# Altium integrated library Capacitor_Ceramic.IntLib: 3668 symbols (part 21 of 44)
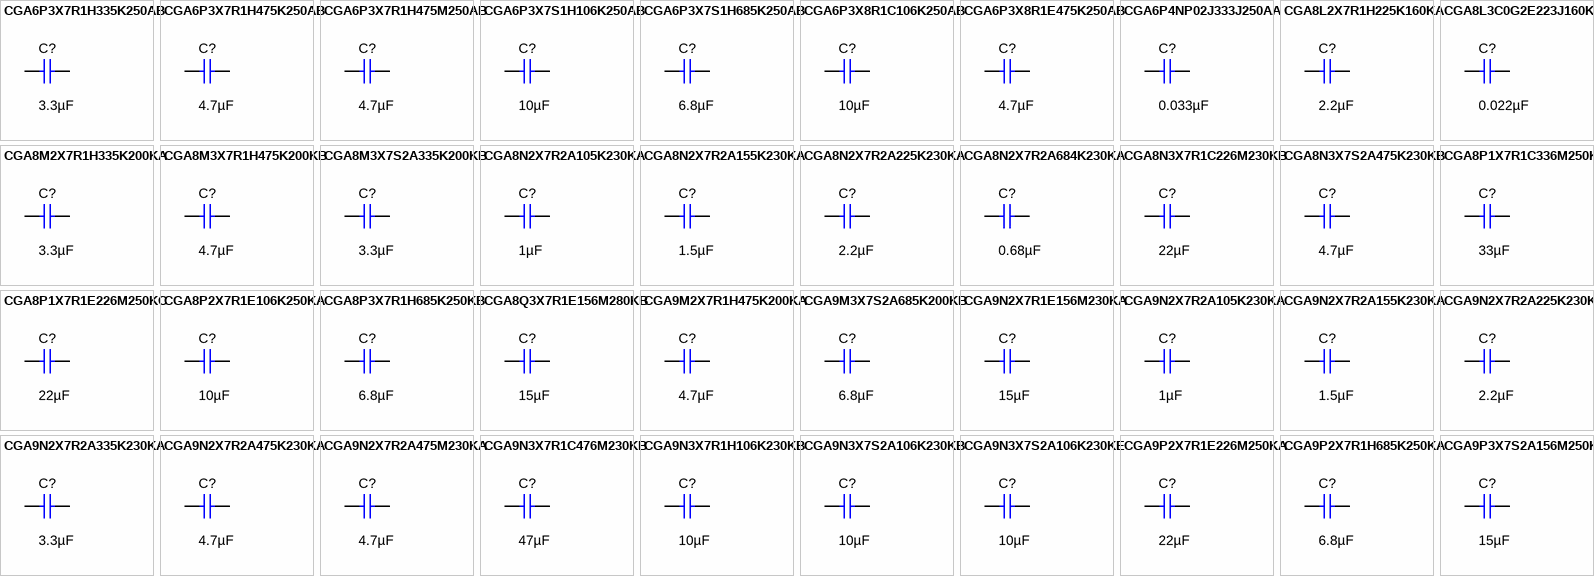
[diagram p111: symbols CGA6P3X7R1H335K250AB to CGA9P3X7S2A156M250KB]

## CGA8L3C0G2E223J160KA
designator C?  ValueDisplayed: 0.022µF  (hidden comment: CGA8L3C0G2E223J160KA)
CAP, CERM, 0.022 µF, 250 V,+/- 5%, C0G/NP0, AEC-Q200 Grade 1, 1812; Manufacturer: TDK; Polarized: N; CompType: Capacitor; Value: 0.022uF; U/M: EA; Cap_F: 0.000000022; Tolerance_%: 5; VDC_V: 250; Value2: 250V; TaMin_C: -55; TaMax_C: 125; Cap_Case: 1812; SizeArea_mm2: 14.4; SizeAreaWB_mm2: 23.1; SizeX_mm: 4.5; SizeY_mm: 3.2; SizeZ_mm: 2.54; AEC Category: Q200; AEC Qualified: Y; AEC Grade: 1
signal-integrity model Cap
simulation model Cap
footprint 1812_254
pins: 1, 2

## CGA8M2X7R1H335K200KA
designator C?  ValueDisplayed: 3.3µF  (hidden comment: CGA8M2X7R1H335K200KA)
CAP, CERM, 3.3 µF, 50 V,+/- 10%, X7R, AEC-Q200 Grade 1, 1812; Manufacturer: TDK; Polarized: N; CompType: Capacitor; Value: 3.3uF; U/M: EA; Cap_F: 0.0000033; Tolerance_%: 10; ESR_ohm: 0.004024; Value1: 0.004024 ohm; VDC_V: 50; Value2: 50V; IRMS_A: 3.82481; TaMin_C: -55; TaMax_C: 125; Cap_Case: 1812; SizeArea_mm2: 14.4; SizeAreaWB_mm2: 23.1; SizeX_mm: 4.5; SizeY_mm: 3.2; SizeZ_mm: 2.2; AEC Category: Q200; AEC Qualified: Y; AEC Grade: 1
signal-integrity model Cap
simulation model Cap
footprint 1812_220
footprint 1812_220M
footprint 1812_220L
pins: 1, 2

## CGA8M3X7R1H475K200KB
designator C?  ValueDisplayed: 4.7µF  (hidden comment: CGA8M3X7R1H475K200KB)
CAP, CERM, 4.7 µF, 50 V,+/- 10%, X7R, AEC-Q200 Grade 1, 1812; Manufacturer: TDK; Polarized: N; CompType: Capacitor; Value: 4.7uF; U/M: EA; Cap_F: 0.0000047; Tolerance_%: 10; ESR_ohm: 0.005172; Value1: 0.005172 ohm; VDC_V: 50; Value2: 50V; IRMS_A: 3.37342; TaMin_C: -55; TaMax_C: 125; Cap_Case: 1812; SizeArea_mm2: 14.4; SizeAreaWB_mm2: 23.1; SizeX_mm: 4.5; SizeY_mm: 3.2; SizeZ_mm: 2.2; AEC Category: Q200; AEC Qualified: Y; AEC Grade: 1
signal-integrity model Cap
simulation model Cap
footprint 1812_220
footprint 1812_220M
footprint 1812_220L
pins: 1, 2

## CGA8M3X7S2A335K200KB
designator C?  ValueDisplayed: 3.3µF  (hidden comment: CGA8M3X7S2A335K200KB)
CAP, CERM, 3.3 µF, 100 V,+/- 10%, X7S, AEC-Q200 Grade 1, 1812; Manufacturer: TDK; Polarized: N; CompType: Capacitor; Value: 3.3uF; U/M: EA; Cap_F: 0.0000033; Tolerance_%: 10; ESR_ohm: 0.004622; Value1: 0.004622 ohm; VDC_V: 100; Value2: 100V; IRMS_A: 3.5689; TaMin_C: -55; TaMax_C: 125; Cap_Case: 1812; SizeArea_mm2: 14.4; SizeAreaWB_mm2: 23.1; SizeX_mm: 4.5; SizeY_mm: 3.2; SizeZ_mm: 2.2; AEC Category: Q200; AEC Qualified: Y; AEC Grade: 1
signal-integrity model Cap
simulation model Cap
footprint 1812_220
footprint 1812_220M
footprint 1812_220L
pins: 1, 2

## CGA8N2X7R2A105K230KA
designator C?  ValueDisplayed: 1µF  (hidden comment: CGA8N2X7R2A105K230KA)
CAP, CERM, 1 µF, 100 V,+/- 10%, X7R, AEC-Q200 Grade 1, 1812; Manufacturer: TDK; Polarized: N; CompType: Capacitor; Value: 1uF; U/M: EA; Cap_F: 0.000001; Tolerance_%: 10; ESR_ohm: 0.005865; Value1: 0.005865 ohm; VDC_V: 100; Value2: 100V; IRMS_A: 3.17165; TaMin_C: -55; TaMax_C: 125; Cap_Case: 1812; SizeArea_mm2: 14.4; SizeAreaWB_mm2: 23.1; SizeX_mm: 4.5; SizeY_mm: 3.2; SizeZ_mm: 2.54; AEC Category: Q200; AEC Qualified: Y; AEC Grade: 1
signal-integrity model Cap
simulation model Cap
footprint 1812_254
pins: 1, 2

## CGA8N2X7R2A155K230KA
designator C?  ValueDisplayed: 1.5µF  (hidden comment: CGA8N2X7R2A155K230KA)
CAP, CERM, 1.5 µF, 100 V,+/- 10%, X7R, AEC-Q200 Grade 1, 1812; Manufacturer: TDK; Polarized: N; CompType: Capacitor; Value: 1.5uF; U/M: EA; Cap_F: 0.0000015; Tolerance_%: 10; ESR_ohm: 0.00449; Value1: 0.00449 ohm; VDC_V: 100; Value2: 100V; IRMS_A: 3.62321; TaMin_C: -55; TaMax_C: 125; Cap_Case: 1812; SizeArea_mm2: 14.4; SizeAreaWB_mm2: 23.1; SizeX_mm: 4.5; SizeY_mm: 3.2; SizeZ_mm: 2.54; AEC Category: Q200; AEC Qualified: Y; AEC Grade: 1
signal-integrity model Cap
simulation model Cap
footprint 1812_254
pins: 1, 2

## CGA8N2X7R2A225K230KA
designator C?  ValueDisplayed: 2.2µF  (hidden comment: CGA8N2X7R2A225K230KA)
CAP, CERM, 2.2 µF, 100 V,+/- 10%, X7R, AEC-Q200 Grade 1, 1812; Manufacturer: TDK; Polarized: N; CompType: Capacitor; Value: 2.2uF; U/M: EA; Cap_F: 0.0000022; Tolerance_%: 10; ESR_ohm: 0.002981; Value1: 0.002981 ohm; VDC_V: 100; Value2: 100V; IRMS_A: 4.44466; TaMin_C: -55; TaMax_C: 125; Cap_Case: 1812; SizeArea_mm2: 14.4; SizeAreaWB_mm2: 23.1; SizeX_mm: 4.5; SizeY_mm: 3.2; SizeZ_mm: 2.54; AEC Category: Q200; AEC Qualified: Y; AEC Grade: 1
signal-integrity model Cap
simulation model Cap
footprint 1812_254
pins: 1, 2

## CGA8N2X7R2A684K230KA
designator C?  ValueDisplayed: 0.68µF  (hidden comment: CGA8N2X7R2A684K230KA)
CAP, CERM, 0.68 µF, 100 V,+/- 10%, X7R, AEC-Q200 Grade 1, 1812; Manufacturer: TDK; Polarized: N; CompType: Capacitor; Value: 0.68uF; U/M: EA; Cap_F: 0.00000068; Tolerance_%: 10; ESR_ohm: 0.007113; Value1: 0.007113 ohm; VDC_V: 100; Value2: 100V; IRMS_A: 2.8819; TaMin_C: -55; TaMax_C: 125; Cap_Case: 1812; SizeArea_mm2: 14.4; SizeAreaWB_mm2: 23.1; SizeX_mm: 4.5; SizeY_mm: 3.2; SizeZ_mm: 2.54; AEC Category: Q200; AEC Qualified: Y; AEC Grade: 1
signal-integrity model Cap
simulation model Cap
footprint 1812_254
pins: 1, 2

## CGA8N3X7R1C226M230KB
designator C?  ValueDisplayed: 22µF  (hidden comment: CGA8N3X7R1C226M230KB)
CAP, CERM, 22 µF, 16 V,+/- 20%, X7R, AEC-Q200 Grade 1, 1812; Manufacturer: TDK; Polarized: N; CompType: Capacitor; Value: 22uF; U/M: EA; Cap_F: 0.000022; Tolerance_%: 20; VDC_V: 16; Value2: 16V; TaMin_C: -55; TaMax_C: 125; Cap_Case: 1812; SizeArea_mm2: 14.4; SizeAreaWB_mm2: 23.1; SizeX_mm: 4.5; SizeY_mm: 3.2; SizeZ_mm: 2.54; AEC Category: Q200; AEC Qualified: Y; AEC Grade: 1; Green_Lifecycle: Active; Green_REACh: Passed
signal-integrity model Cap
simulation model Cap
footprint 1812_254
pins: 1, 2

## CGA8N3X7S2A475K230KB
designator C?  ValueDisplayed: 4.7µF  (hidden comment: CGA8N3X7S2A475K230KB)
CAP, CERM, 4.7 µF, 100 V,+/- 10%, X7S, AEC-Q200 Grade 1, 1812; Manufacturer: TDK; Polarized: N; CompType: Capacitor; Value: 4.7uF; U/M: EA; Cap_F: 0.0000047; Tolerance_%: 10; ESR_ohm: 0.00515; Value1: 0.00515 ohm; VDC_V: 100; Value2: 100V; IRMS_A: 3.38056; TaMin_C: -55; TaMax_C: 125; Cap_Case: 1812; SizeArea_mm2: 14.4; SizeAreaWB_mm2: 23.1; SizeX_mm: 4.5; SizeY_mm: 3.2; SizeZ_mm: 2.54; AEC Category: Q200; AEC Qualified: Y; AEC Grade: 1
signal-integrity model Cap
simulation model Cap
footprint 1812_254
pins: 1, 2

## CGA8P1X7R1C336M250KC
designator C?  ValueDisplayed: 33µF  (hidden comment: CGA8P1X7R1C336M250KC)
CAP, CERM, 33 µF, 16 V,+/- 20%, X7R, AEC-Q200 Grade 1, 1812; Manufacturer: TDK; Polarized: N; CompType: Capacitor; Value: 33uF; U/M: EA; Cap_F: 0.000033; Tolerance_%: 20; ESR_ohm: 0.002427; Value1: 0.002427 ohm; VDC_V: 16; Value2: 16V; IRMS_A: 4.92344; TaMin_C: -55; TaMax_C: 125; Cap_Case: 1812; SizeArea_mm2: 14.4; SizeAreaWB_mm2: 23.1; SizeX_mm: 4.5; SizeY_mm: 3.2; SizeZ_mm: 2.8; AEC Category: Q200; AEC Qualified: Y; AEC Grade: 1
signal-integrity model Cap
simulation model Cap
footprint 1812_280
footprint 1812_280M
footprint 1812_280L
pins: 1, 2

## CGA8P1X7R1E226M250KC
designator C?  ValueDisplayed: 22µF  (hidden comment: CGA8P1X7R1E226M250KC)
CAP, CERM, 22 µF, 25 V,+/- 20%, X7R, AEC-Q200 Grade 1, 1812; Manufacturer: TDK; Polarized: N; CompType: Capacitor; Value: 22uF; U/M: EA; Cap_F: 0.000022; Tolerance_%: 20; ESR_ohm: 0.002434; Value1: 0.002434 ohm; VDC_V: 25; Value2: 25V; IRMS_A: 4.91649; TaMin_C: -55; TaMax_C: 125; Cap_Case: 1812; SizeArea_mm2: 14.4; SizeAreaWB_mm2: 23.1; SizeX_mm: 4.5; SizeY_mm: 3.2; SizeZ_mm: 2.8; AEC Category: Q200; AEC Qualified: Y; AEC Grade: 1
signal-integrity model Cap
simulation model Cap
footprint 1812_280
footprint 1812_280M
footprint 1812_280L
pins: 1, 2

## CGA8P2X7R1E106K250KA
designator C?  ValueDisplayed: 10µF  (hidden comment: CGA8P2X7R1E106K250KA)
CAP, CERM, 10 µF, 25 V,+/- 10%, X7R, AEC-Q200 Grade 1, 1812; Manufacturer: TDK; Polarized: N; CompType: Capacitor; Value: 10uF; U/M: EA; Cap_F: 0.00001; Tolerance_%: 10; ESR_ohm: 0.00174; Value1: 0.00174 ohm; VDC_V: 25; Value2: 25V; IRMS_A: 5.81481; TaMin_C: -55; TaMax_C: 125; Cap_Case: 1812; SizeArea_mm2: 14.4; SizeAreaWB_mm2: 23.1; SizeX_mm: 4.5; SizeY_mm: 3.2; SizeZ_mm: 2.8; AEC Category: Q200; AEC Qualified: Y; AEC Grade: 1
signal-integrity model Cap
simulation model Cap
footprint 1812_280
footprint 1812_280M
footprint 1812_280L
pins: 1, 2

## CGA8P3X7R1H685K250KB
designator C?  ValueDisplayed: 6.8µF  (hidden comment: CGA8P3X7R1H685K250KB)
CAP, CERM, 6.8 µF, 50 V,+/- 10%, X7R, AEC-Q200 Grade 1, 1812; Manufacturer: TDK; Polarized: N; CompType: Capacitor; Value: 6.8uF; U/M: EA; Cap_F: 0.0000068; Tolerance_%: 10; ESR_ohm: 0.002621; Value1: 0.002621 ohm; VDC_V: 50; Value2: 50V; IRMS_A: 4.73771; TaMin_C: -55; TaMax_C: 125; Cap_Case: 1812; SizeArea_mm2: 14.4; SizeAreaWB_mm2: 23.1; SizeX_mm: 4.5; SizeY_mm: 3.2; SizeZ_mm: 2.8; AEC Category: Q200; AEC Qualified: Y; AEC Grade: 1
signal-integrity model Cap
simulation model Cap
footprint 1812_280
footprint 1812_280M
footprint 1812_280L
pins: 1, 2

## CGA8Q3X7R1E156M280KB
designator C?  ValueDisplayed: 15µF  (hidden comment: CGA8Q3X7R1E156M280KB)
CAP, CERM, 15 µF, 25 V,+/- 20%, X7R, AEC-Q200 Grade 1, 1812; Manufacturer: TDK; Polarized: N; CompType: Capacitor; Value: 15uF; U/M: EA; Cap_F: 0.000015; Tolerance_%: 20; ESR_ohm: 0.002488; Value1: 0.002488 ohm; VDC_V: 25; Value2: 25V; IRMS_A: 4.86254; TaMin_C: -55; TaMax_C: 125; Cap_Case: 1812; SizeArea_mm2: 14.4; SizeAreaWB_mm2: 23.1; SizeX_mm: 4.5; SizeY_mm: 3.2; AEC Category: Q200; AEC Qualified: Y; AEC Grade: 1
signal-integrity model Cap
simulation model Cap
footprint 1812_320
footprint 1812_320M
footprint 1812_320L
pins: 1, 2

## CGA9M2X7R1H475K200KA
designator C?  ValueDisplayed: 4.7µF  (hidden comment: CGA9M2X7R1H475K200KA)
CAP, CERM, 4.7 µF, 50 V,+/- 10%, X7R, AEC-Q200 Grade 1, 2220; Manufacturer: TDK; Polarized: N; CompType: Capacitor; Value: 4.7uF; U/M: EA; Cap_F: 0.0000047; Tolerance_%: 10; ESR_ohm: 0.003808; Value1: 0.003808 ohm; VDC_V: 50; Value2: 50V; IRMS_A: 4.67908; TaMin_C: -55; TaMax_C: 125; Cap_Case: 2220; SizeArea_mm2: 28.5; SizeAreaWB_mm2: 53.9; SizeX_mm: 5.7; SizeY_mm: 5; SizeZ_mm: 2.2; AEC Category: Q200; AEC Qualified: Y; AEC Grade: 1
signal-integrity model Cap
simulation model Cap
footprint 2220_220
footprint 2220_220M
footprint 2220_220L
pins: 1, 2

## CGA9M3X7S2A685K200KB
designator C?  ValueDisplayed: 6.8µF  (hidden comment: CGA9M3X7S2A685K200KB)
CAP, CERM, 6.8 µF, 100 V,+/- 10%, X7S, AEC-Q200 Grade 1, 2220; Manufacturer: TDK; Polarized: N; CompType: Capacitor; Value: 6.8uF; U/M: EA; Cap_F: 0.0000068; Tolerance_%: 10; ESR_ohm: 0.003492; Value1: 0.003492 ohm; VDC_V: 100; Value2: 100V; IRMS_A: 4.88574; TaMin_C: -55; TaMax_C: 125; Cap_Case: 2220; SizeArea_mm2: 28.5; SizeAreaWB_mm2: 53.9; SizeX_mm: 5.7; SizeY_mm: 5; SizeZ_mm: 2.2; AEC Category: Q200; AEC Qualified: Y; AEC Grade: 1
signal-integrity model Cap
simulation model Cap
footprint 2220_220
footprint 2220_220M
footprint 2220_220L
pins: 1, 2

## CGA9N2X7R1E156M230KA
designator C?  ValueDisplayed: 15µF  (hidden comment: CGA9N2X7R1E156M230KA)
CAP, CERM, 15 µF, 25 V,+/- 20%, X7R, AEC-Q200 Grade 1, 2220; Manufacturer: TDK; Polarized: N; CompType: Capacitor; Value: 15uF; U/M: EA; Cap_F: 0.000015; Tolerance_%: 20; ESR_ohm: 0.002725; Value1: 0.002725 ohm; VDC_V: 25; Value2: 25V; IRMS_A: 5.53023; TaMin_C: -55; TaMax_C: 125; Cap_Case: 2220; SizeArea_mm2: 28.5; SizeAreaWB_mm2: 53.9; SizeX_mm: 5.7; SizeY_mm: 5; SizeZ_mm: 2.5; AEC Category: Q200; AEC Qualified: Y; AEC Grade: 1
signal-integrity model Cap
simulation model Cap
footprint 2220_250
footprint 2220_250M
footprint 2220_250L
pins: 1, 2

## CGA9N2X7R2A105K230KA
designator C?  ValueDisplayed: 1µF  (hidden comment: CGA9N2X7R2A105K230KA)
CAP, CERM, 1 µF, 100 V,+/- 10%, X7R, AEC-Q200 Grade 1, 2220; Manufacturer: TDK; Polarized: N; CompType: Capacitor; Value: 1uF; U/M: EA; Cap_F: 0.000001; Tolerance_%: 10; ESR_ohm: 0.0056; Value1: 0.0056 ohm; VDC_V: 100; Value2: 100V; IRMS_A: 3.86315; TaMin_C: -55; TaMax_C: 125; Cap_Case: 2220; SizeArea_mm2: 28.5; SizeAreaWB_mm2: 53.9; SizeX_mm: 5.7; SizeY_mm: 5; SizeZ_mm: 2.5; AEC Category: Q200; AEC Qualified: Y; AEC Grade: 1
signal-integrity model Cap
simulation model Cap
footprint 2220_250
footprint 2220_250M
footprint 2220_250L
pins: 1, 2

## CGA9N2X7R2A155K230KA
designator C?  ValueDisplayed: 1.5µF  (hidden comment: CGA9N2X7R2A155K230KA)
CAP, CERM, 1.5 µF, 100 V,+/- 10%, X7R, AEC-Q200 Grade 1, 2220; Manufacturer: TDK; Polarized: N; CompType: Capacitor; Value: 1.5uF; U/M: EA; Cap_F: 0.0000015; Tolerance_%: 10; ESR_ohm: 0.00441; Value1: 0.00441 ohm; VDC_V: 100; Value2: 100V; IRMS_A: 4.35148; TaMin_C: -55; TaMax_C: 125; Cap_Case: 2220; SizeArea_mm2: 28.5; SizeAreaWB_mm2: 53.9; SizeX_mm: 5.7; SizeY_mm: 5; SizeZ_mm: 2.5; AEC Category: Q200; AEC Qualified: Y; AEC Grade: 1
signal-integrity model Cap
simulation model Cap
footprint 2220_250
footprint 2220_250M
footprint 2220_250L
pins: 1, 2

## CGA9N2X7R2A225K230KA
designator C?  ValueDisplayed: 2.2µF  (hidden comment: CGA9N2X7R2A225K230KA)
CAP, CERM, 2.2 µF, 100 V,+/- 10%, X7R, AEC-Q200 Grade 1, 2220; Manufacturer: TDK; Polarized: N; CompType: Capacitor; Value: 2.2uF; U/M: EA; Cap_F: 0.0000022; Tolerance_%: 10; ESR_ohm: 0.002841; Value1: 0.002841 ohm; VDC_V: 100; Value2: 100V; IRMS_A: 5.41912; TaMin_C: -55; TaMax_C: 125; Cap_Case: 2220; SizeArea_mm2: 28.5; SizeAreaWB_mm2: 53.9; SizeX_mm: 5.7; SizeY_mm: 5; SizeZ_mm: 2.5; AEC Category: Q200; AEC Qualified: Y; AEC Grade: 1
signal-integrity model Cap
simulation model Cap
footprint 2220_250
footprint 2220_250M
footprint 2220_250L
pins: 1, 2

## CGA9N2X7R2A335K230KA
designator C?  ValueDisplayed: 3.3µF  (hidden comment: CGA9N2X7R2A335K230KA)
CAP, CERM, 3.3 µF, 100 V,+/- 10%, X7R, AEC-Q200 Grade 1, 2220; Manufacturer: TDK; Polarized: N; CompType: Capacitor; Value: 3.3uF; U/M: EA; Cap_F: 0.0000033; Tolerance_%: 10; ESR_ohm: 0.002585; Value1: 0.002585 ohm; VDC_V: 100; Value2: 100V; IRMS_A: 5.68031; TaMin_C: -55; TaMax_C: 125; Cap_Case: 2220; SizeArea_mm2: 28.5; SizeAreaWB_mm2: 53.9; SizeX_mm: 5.7; SizeY_mm: 5; SizeZ_mm: 2.5; AEC Category: Q200; AEC Qualified: Y; AEC Grade: 1
signal-integrity model Cap
simulation model Cap
footprint 2220_250
footprint 2220_250M
footprint 2220_250L
pins: 1, 2

## CGA9N2X7R2A475K230KA
designator C?  ValueDisplayed: 4.7µF  (hidden comment: CGA9N2X7R2A475K230KA)
CAP, CERM, 4.7 µF, 100 V,+/- 10%, X7R, AEC-Q200 Grade 1, 2220; Manufacturer: TDK; Polarized: N; CompType: Capacitor; Value: 4.7uF; U/M: EA; Cap_F: 0.0000047; Tolerance_%: 10; ESR_ohm: 0.002349; Value1: 0.002349 ohm; VDC_V: 100; Value2: 100V; IRMS_A: 5.95718; TaMin_C: -55; TaMax_C: 125; Cap_Case: 2220; SizeArea_mm2: 28.5; SizeAreaWB_mm2: 53.9; SizeX_mm: 5.7; SizeY_mm: 5; SizeZ_mm: 2.5; AEC Category: Q200; AEC Qualified: Y; AEC Grade: 1
signal-integrity model Cap
simulation model Cap
footprint 2220_250
footprint 2220_250M
footprint 2220_250L
pins: 1, 2

## CGA9N2X7R2A475M230KA
designator C?  ValueDisplayed: 4.7µF  (hidden comment: CGA9N2X7R2A475M230KA)
CAP, CERM, 4.7 µF, 100 V,+/- 20%, X7R, AEC-Q200 Grade 1, 2220; Manufacturer: TDK; Polarized: N; CompType: Capacitor; Value: 4.7uF; U/M: EA; Cap_F: 0.0000047; Tolerance_%: 20; VDC_V: 100; Value2: 100V; TaMin_C: -55; TaMax_C: 125; Cap_Case: 2220; SizeArea_mm2: 28.5; SizeAreaWB_mm2: 53.9; SizeX_mm: 5.7; SizeY_mm: 5; SizeZ_mm: 2.5; AEC Category: Q200; AEC Qualified: Y; AEC Grade: 1
signal-integrity model Cap
simulation model Cap
footprint 2220_250
footprint 2220_250M
footprint 2220_250L
pins: 1, 2

## CGA9N3X7R1C476M230KB
designator C?  ValueDisplayed: 47µF  (hidden comment: CGA9N3X7R1C476M230KB)
CAP, CERM, 47 µF, 16 V,+/- 20%, X7R, AEC-Q200 Grade 1, 2220; Manufacturer: TDK; Polarized: N; CompType: Capacitor; Value: 47uF; U/M: EA; Cap_F: 0.000047; Tolerance_%: 20; ESR_ohm: 0.003162; Value1: 0.003162 ohm; VDC_V: 16; Value2: 16V; IRMS_A: 5.13436; TaMin_C: -55; TaMax_C: 125; Cap_Case: 2220; SizeArea_mm2: 28.5; SizeAreaWB_mm2: 53.9; SizeX_mm: 5.7; SizeY_mm: 5; SizeZ_mm: 2.5; AEC Category: Q200; AEC Qualified: Y; AEC Grade: 1
signal-integrity model Cap
simulation model Cap
footprint 2220_250
footprint 2220_250M
footprint 2220_250L
pins: 1, 2

## CGA9N3X7R1H106K230KB
designator C?  ValueDisplayed: 10µF  (hidden comment: CGA9N3X7R1H106K230KB)
CAP, CERM, 10 µF, 50 V,+/- 10%, X7R, AEC-Q200 Grade 1, 2220; Manufacturer: TDK; Polarized: N; CompType: Capacitor; Value: 10uF; U/M: EA; Cap_F: 0.00001; Tolerance_%: 10; ESR_ohm: 0.002611; Value1: 0.002611 ohm; VDC_V: 50; Value2: 50V; IRMS_A: 5.65008; TaMin_C: -55; TaMax_C: 125; Cap_Case: 2220; SizeArea_mm2: 28.5; SizeAreaWB_mm2: 53.9; SizeX_mm: 5.7; SizeY_mm: 5; SizeZ_mm: 2.5; AEC Category: Q200; AEC Qualified: Y; AEC Grade: 1; Green_Lifecycle: Active; Green_REACh: Passed
signal-integrity model Cap
simulation model Cap
footprint 2220_250
footprint 2220_250M
footprint 2220_250L
pins: 1, 2

## CGA9N3X7S2A106K230KB
designator C?  ValueDisplayed: 10µF  (hidden comment: CGA9N3X7S2A106K230KB)
CAP, CERM, 10 µF, 100 V,+/- 10%, X7S, AEC-Q200 Grade 1, 2220; Manufacturer: TDK; Polarized: N; CompType: Capacitor; Value: 10uF; U/M: EA; Cap_F: 0.00001; Tolerance_%: 10; ESR_ohm: 0.003179; Value1: 0.003179 ohm; VDC_V: 100; Value2: 100V; IRMS_A: 5.11992; TaMin_C: -55; TaMax_C: 125; Cap_Case: 2220; SizeArea_mm2: 28.5; SizeAreaWB_mm2: 53.9; SizeX_mm: 5.7; SizeY_mm: 5; SizeZ_mm: 2.5; AEC Category: Q200; AEC Qualified: Y; AEC Grade: 1; Green_Lifecycle: Active; Green_REACh: Passed
signal-integrity model Cap
simulation model Cap
footprint 2220_250
footprint 2220_250M
footprint 2220_250L
pins: 1, 2

## CGA9N3X7S2A106K230KE
designator C?  ValueDisplayed: 10µF  (hidden comment: CGA9N3X7S2A106K230KE)
CAP, CERM, 10 µF, 100 V,+/- 10%, X7S, AEC-Q200 Grade 1, 2220; Manufacturer: TDK; Polarized: N; CompType: Capacitor; Value: 10uF; U/M: EA; Cap_F: 0.00001; Tolerance_%: 10; VDC_V: 100; Value2: 100V; TaMin_C: -55; TaMax_C: 125; Cap_Case: 2220; SizeArea_mm2: 28.5; SizeAreaWB_mm2: 53.9; SizeX_mm: 5.7; SizeY_mm: 5; SizeZ_mm: 2.8; AEC Category: Q200; AEC Qualified: Y; AEC Grade: 1
signal-integrity model Cap
simulation model Cap
footprint 2220_280
footprint 2220_280M
footprint 2220_280L
pins: 1, 2

## CGA9P2X7R1E226M250KA
designator C?  ValueDisplayed: 22µF  (hidden comment: CGA9P2X7R1E226M250KA)
CAP, CERM, 22 µF, 25 V,+/- 20%, X7R, AEC-Q200 Grade 1, 2220; Manufacturer: TDK; Polarized: N; CompType: Capacitor; Value: 22uF; U/M: EA; Cap_F: 0.000022; Tolerance_%: 20; VDC_V: 25; Value2: 25V; TaMin_C: -55; TaMax_C: 125; Cap_Case: 2220; SizeArea_mm2: 28.5; SizeAreaWB_mm2: 53.9; SizeX_mm: 5.7; SizeY_mm: 5; SizeZ_mm: 2.8; AEC Category: Q200; AEC Qualified: Y; AEC Grade: 1
signal-integrity model Cap
simulation model Cap
footprint 2220_280
footprint 2220_280M
footprint 2220_280L
pins: 1, 2

## CGA9P2X7R1H685K250KA
designator C?  ValueDisplayed: 6.8µF  (hidden comment: CGA9P2X7R1H685K250KA)
CAP, CERM, 6.8 µF, 50 V,+/- 10%, X7R, AEC-Q200 Grade 1, 2220; Manufacturer: TDK; Polarized: N; CompType: Capacitor; Value: 6.8uF; U/M: EA; Cap_F: 0.0000068; Tolerance_%: 10; ESR_ohm: 0.002126; Value1: 0.002126 ohm; VDC_V: 50; Value2: 50V; IRMS_A: 6.26198; TaMin_C: -55; TaMax_C: 125; Cap_Case: 2220; SizeArea_mm2: 28.5; SizeAreaWB_mm2: 53.9; SizeX_mm: 5.7; SizeY_mm: 5; SizeZ_mm: 2.8; AEC Category: Q200; AEC Qualified: Y; AEC Grade: 1
signal-integrity model Cap
simulation model Cap
footprint 2220_280
footprint 2220_280M
footprint 2220_280L
pins: 1, 2

## CGA9P3X7S2A156M250KB
designator C?  ValueDisplayed: 15µF  (hidden comment: CGA9P3X7S2A156M250KB)
CAP, CERM, 15 µF, 100 V,+/- 20%, X7S, AEC-Q200 Grade 1, 2220; Manufacturer: TDK; Polarized: N; CompType: Capacitor; Value: 15uF; U/M: EA; Cap_F: 0.000015; Tolerance_%: 20; ESR_ohm: 0.002642; Value1: 0.002642 ohm; VDC_V: 100; Value2: 100V; IRMS_A: 5.61617; TaMin_C: -55; TaMax_C: 125; Cap_Case: 2220; SizeArea_mm2: 28.5; SizeAreaWB_mm2: 53.9; SizeX_mm: 5.7; SizeY_mm: 5; SizeZ_mm: 2.8; AEC Category: Q200; AEC Qualified: Y; AEC Grade: 1
signal-integrity model Cap
simulation model Cap
footprint 2220_280
footprint 2220_280M
footprint 2220_280L
pins: 1, 2

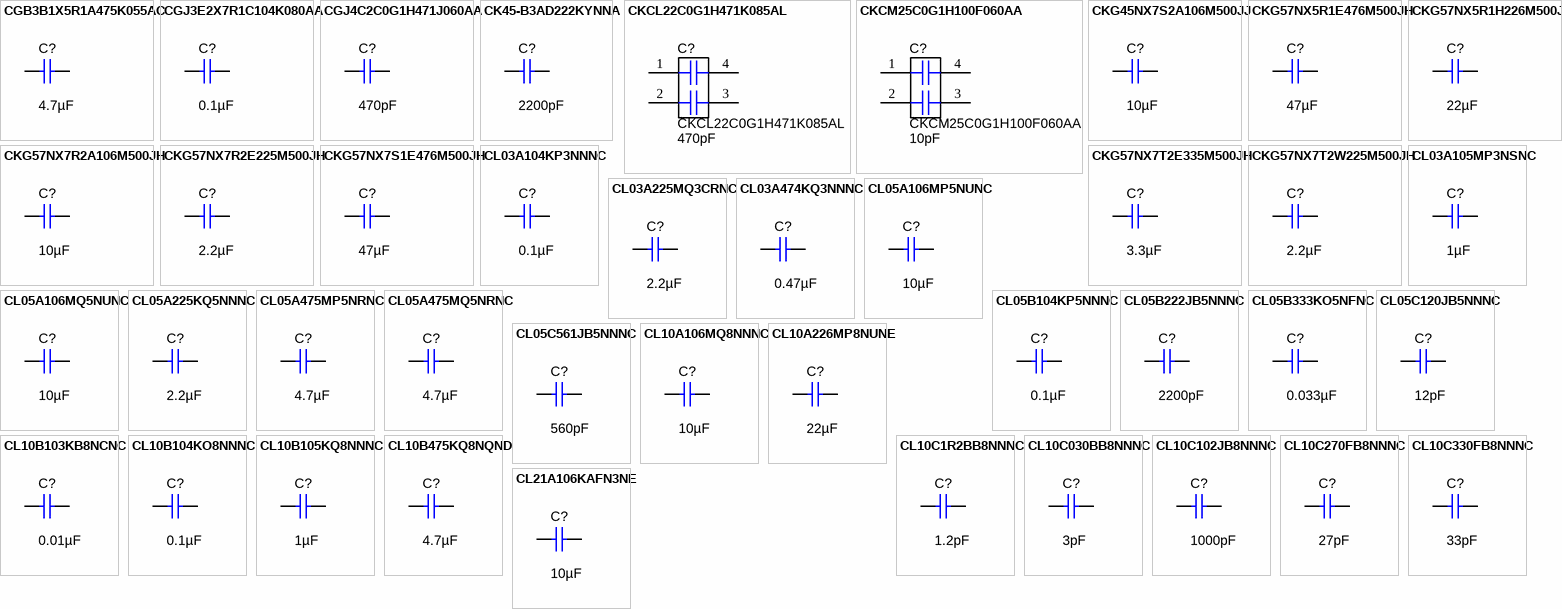
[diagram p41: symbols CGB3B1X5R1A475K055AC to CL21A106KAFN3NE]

## CGB3B1X5R1A475K055AC
designator C?  ValueDisplayed: 4.7µF  (hidden comment: CGB3B1X5R1A475K055AC)
CAP, CERM, 4.7 µF, 10 V,+/- 10%, X5R, 0603; Manufacturer: TDK; Polarized: N; CompType: Capacitor; Value: 4.7uF; U/M: EA; Cap_F: 0.0000047; Tolerance_%: 10; Value2: 10V; TaMin_C: -55; TaMax_C: 85; Cap_Case: 0603; SizeArea_mm2: 1.28; SizeAreaWB_mm2: 4.68; SizeX_mm: 1.6; SizeY_mm: 0.8; SizeZ_mm: 1; AEC Category: Q200; Green_Lifecycle: Active; Green_REACh: Passed
signal-integrity model Cap
simulation model Cap
footprint 0603
footprint 0603M
footprint 0603L
footprint 0603_HV
footprint 0603S
pins: 1, 2

## CGJ3E2X7R1C104K080AA
designator C?  ValueDisplayed: 0.1µF  (hidden comment: CGJ3E2X7R1C104K080AA)
CAP, CERM, 0.1 µF, 16 V,+/- 10%, X7R, AEC-Q200 Grade 1, 0603; Manufacturer: TDK; Polarized: N; CompType: Capacitor; Value: 0.1uF; U/M: EA; Cap_F: 0.0000001; Tolerance_%: 10; VDC_V: 16; Value2: 16V; TaMin_C: -55; TaMax_C: 125; Cap_Case: 0603; SizeArea_mm2: 1.28; SizeAreaWB_mm2: 4.68; SizeX_mm: 1.6; SizeY_mm: 0.8; SizeZ_mm: 1; AEC Category: Q200; AEC Qualified: Y; Green_Lifecycle: NRND; Green_REACh: Passed
signal-integrity model Cap
simulation model Cap
footprint 0603
footprint 0603M
footprint 0603L
footprint 0603_HV
footprint 0603S
pins: 1, 2

## CGJ4C2C0G1H471J060AA
designator C?  ValueDisplayed: 470pF  (hidden comment: CGJ4C2C0G1H471J060AA)
CAP, CERM, 470 pF, 50 V,+/- 5%, C0G/NP0, 0805; Manufacturer: TDK; Polarized: N; CompType: Capacitor; Value: 470pF; U/M: EA; Cap_F: 0.00000000047; Tolerance_%: 5; VDC_V: 50; Value2: 50V; TaMin_C: -55; TaMax_C: 125; Cap_Case: 0805; SizeArea_mm2: 2.5; SizeAreaWB_mm2: 6.75; SizeX_mm: 2; SizeY_mm: 1.25; SizeZ_mm: 1.45; AEC Category: Q200; Green_Lifecycle: NRND; Green_REACh: Passed
signal-integrity model Cap
simulation model Cap
footprint 0805_HV
footprint 0805_HV1
footprint 0805
footprint 0805M
footprint 0805L
pins: 1, 2

## CK45-B3AD222KYNNA
designator C?  ValueDisplayed: 2200pF  (hidden comment: CK45-B3AD222KYNNA)
CAP, CERM, 2200 pF, 1000 V,+/- 10%, B, D8.5xT5mm; Manufacturer: TDK; Polarized: N; CompType: Capacitor; Value: 2200pF; U/M: EA; Cap_F: 0.0000000022; Tolerance_%: 10; VDC_V: 1000; Value2: 1000V; TaMin_C: -25; TaMax_C: 105; Cap_Case: 8.5x5x12.5mm; SizeArea_mm2: 42.5; SizeAreaWB_mm2: 73.5; SizeX_mm: 8.5; SizeY_mm: 5; SizeZ_mm: 12.5; AEC Category: Q200
signal-integrity model Cap
simulation model Cap
footprint CK45_850x500x1250
pins: 1, 2

## CKCL22C0G1H471K085AL
designator C?  ValueDisplayed: 470pF
CAP, CERM, 470 pF, 50 V,+/- 10%, C0G/NP0, AEC-Q200 Grade 1, 2x1.25mm; Manufacturer: TDK; SymbolCreator: Altium; CompType: Capacitor; U/M: EA; Cap_F: 0.00000000047; Value: 470pF; Tolerance_%: 10; VDC_V: 50; Value2: 50V; TaMin_C: -55; TaMax_C: 125; Polarized: N; Cap_Case: 0805; SizeArea_mm2: 2.5; SizeAreaWB_mm2: 6.75; SizeX_mm: 2; SizeY_mm: 1.25; SizeZ_mm: 1; AEC Category: Q200; AEC Qualified: Y
footprint CKCL22_085
pins: 1, 2, 3, 4

## CKCM25C0G1H100F060AA
designator C?  ValueDisplayed: 10pF
CAP, CERM, 10 pF, 50 V,+/- 10%, C0G/NP0, 1.37x1mm; Manufacturer: TDK; SymbolCreator: Altium; CompType: Capacitor; U/M: EA; Cap_F: 0.00000000001; Value: 10pF; Tolerance_%: 10; VDC_V: 50; Value2: 50V; TaMin_C: -55; TaMax_C: 125; Polarized: N; Cap_Case: 0504; SizeArea_mm2: 1.37; SizeAreaWB_mm2: 4.74; SizeX_mm: 1; SizeZ_mm: 0.7; AEC Category: Q200
footprint CKCM25_060
pins: 1, 2, 3, 4

## CKG45NX7S2A106M500JJ
designator C?  ValueDisplayed: 10µF  (hidden comment: CKG45NX7S2A106M500JJ)
CAP, CERM, 10 µF, 100 V,+/- 20%, X7S, AEC-Q200 Grade 1, 1812; Manufacturer: TDK; Polarized: N; CompType: Capacitor; Value: 10uF; U/M: EA; Cap_F: 0.00001; Tolerance_%: 20; VDC_V: 100; Value2: 100V; TaMin_C: -55; TaMax_C: 125; Cap_Case: 1812; SizeArea_mm2: 17.5; SizeAreaWB_mm2: 38.5; SizeX_mm: 5; SizeY_mm: 3.5; SizeZ_mm: 5.5; AEC Category: Q200; AEC Qualified: Y; AEC Grade: 1
signal-integrity model Cap
simulation model Cap
footprint CKG45N_500
pins: 1, 2

## CKG57NX5R1E476M500JH
designator C?  ValueDisplayed: 47µF  (hidden comment: CKG57NX5R1E476M500JH)
CAP, CERM, 47 µF, 25 V,+/- 20%, X5R, 6x5x5mm; Manufacturer: TDK; Polarized: N; CompType: Capacitor; Value: 47uF; U/M: EA; Cap_F: 0.000047; Tolerance_%: 20; VDC_V: 25; Value2: 25V; TaMin_C: -55; TaMax_C: 85; Cap_Case: 2220; SizeArea_mm2: 30; SizeAreaWB_mm2: 56; SizeX_mm: 6; SizeY_mm: 5; SizeZ_mm: 5.5; AEC Category: Q200
signal-integrity model Cap
simulation model Cap
footprint CKG57N
pins: 1, 2

## CKG57NX5R1H226M500JH
designator C?  ValueDisplayed: 22µF  (hidden comment: CKG57NX5R1H226M500JH)
CAP, CERM, 22 µF, 50 V,+/- 20%, X5R, 6x5x5mm; Manufacturer: TDK; Polarized: N; CompType: Capacitor; Value: 22uF; U/M: EA; Cap_F: 0.000022; Tolerance_%: 20; VDC_V: 50; Value2: 50V; TaMin_C: -55; TaMax_C: 85; Cap_Case: 2220; SizeArea_mm2: 30; SizeAreaWB_mm2: 56; SizeX_mm: 6; SizeY_mm: 5; SizeZ_mm: 5.5; AEC Category: Q200
signal-integrity model Cap
simulation model Cap
footprint CKG57N
pins: 1, 2

## CKG57NX7R2A106M500JH
designator C?  ValueDisplayed: 10µF  (hidden comment: CKG57NX7R2A106M500JH)
CAP, CERM, 10 µF, 100 V,+/- 20%, X7R, 6x5x5mm; Manufacturer: TDK; Polarized: N; CompType: Capacitor; Value: 10uF; U/M: EA; Cap_F: 0.00001; Tolerance_%: 20; VDC_V: 100; Value2: 100V; TaMin_C: -55; TaMax_C: 125; Cap_Case: 2220; SizeArea_mm2: 30; SizeAreaWB_mm2: 56; SizeX_mm: 6; SizeY_mm: 5; SizeZ_mm: 5.5; AEC Category: Q200
signal-integrity model Cap
simulation model Cap
footprint CKG57N
pins: 1, 2

## CKG57NX7R2E225M500JH
designator C?  ValueDisplayed: 2.2µF  (hidden comment: CKG57NX7R2E225M500JH)
CAP, CERM, 2.2 µF, 250 V,+/- 20%, X7R, AEC-Q200 Grade 1, 6x5x5mm; Manufacturer: TDK; Polarized: N; CompType: Capacitor; Value: 2.2uF; U/M: EA; Cap_F: 0.0000022; Tolerance_%: 20; VDC_V: 250; Value2: 250V; TaMin_C: -55; TaMax_C: 125; Cap_Case: 2220; SizeArea_mm2: 30; SizeAreaWB_mm2: 56; SizeX_mm: 6; SizeY_mm: 5; SizeZ_mm: 5.5; AEC Category: Q200; AEC Qualified: Y; AEC Grade: 1
signal-integrity model Cap
simulation model Cap
footprint CKG57N
pins: 1, 2

## CKG57NX7S1E476M500JH
designator C?  ValueDisplayed: 47µF  (hidden comment: CKG57NX7S1E476M500JH)
CAP, CERM, 47 µF, 25 V,+/- 20%, X7S, 6x5x5mm; Manufacturer: TDK; Polarized: N; CompType: Capacitor; Value: 47uF; U/M: EA; Cap_F: 0.000047; Tolerance_%: 20; VDC_V: 25; Value2: 25V; TaMin_C: -55; TaMax_C: 125; Cap_Case: 2220; SizeArea_mm2: 30; SizeAreaWB_mm2: 56; SizeX_mm: 6; SizeY_mm: 5; SizeZ_mm: 5.5; AEC Category: Q200
signal-integrity model Cap
simulation model Cap
footprint CKG57N
pins: 1, 2

## CKG57NX7T2E335M500JH
designator C?  ValueDisplayed: 3.3µF  (hidden comment: CKG57NX7T2E335M500JH)
CAP, CERM, 3.3 µF, 250 V,+/- 20%, X7T, AEC-Q200 Grade 1, 6x5x5mm; Manufacturer: TDK; Polarized: N; CompType: Capacitor; Value: 3.3uF; U/M: EA; Cap_F: 0.0000033; Tolerance_%: 20; VDC_V: 250; Value2: 250V; TaMin_C: -55; TaMax_C: 125; Cap_Case: 2220; SizeArea_mm2: 30; SizeAreaWB_mm2: 56; SizeX_mm: 6; SizeY_mm: 5; SizeZ_mm: 5.5; AEC Category: Q200; AEC Qualified: Y; AEC Grade: 1
signal-integrity model Cap
simulation model Cap
footprint CKG57N
pins: 1, 2

## CKG57NX7T2W225M500JH
designator C?  ValueDisplayed: 2.2µF  (hidden comment: CKG57NX7T2W225M500JH)
CAP, CERM, 2.2 µF, 450 V,+/- 20%, X7T, AEC-Q200 Grade 1, 6x5x5mm; Manufacturer: TDK; Polarized: N; CompType: Capacitor; Value: 2.2uF; U/M: EA; Cap_F: 0.0000022; Tolerance_%: 20; VDC_V: 450; Value2: 450V; TaMin_C: -55; TaMax_C: 125; Cap_Case: 2220; SizeArea_mm2: 30; SizeAreaWB_mm2: 56; SizeX_mm: 6; SizeY_mm: 5; SizeZ_mm: 5.5; AEC Category: Q200; AEC Qualified: Y; AEC Grade: 1
signal-integrity model Cap
simulation model Cap
footprint CKG57N
pins: 1, 2

## CL03A104KP3NNNC
designator C?  ValueDisplayed: 0.1µF  (hidden comment: CL03A104KP3NNNC)
CAP, CERM, 0.1 µF, 10 V,+/- 10%, X5R, 0201; Manufacturer: Samsung Electro-Mechanics; Polarized: N; CompType: Capacitor; Value: 0.1uF; U/M: EA; Cap_F: 0.0000001; Tolerance_%: 10; Value2: 10V; TaMin_C: -55; TaMax_C: 85; Cap_Case: 0201; SizeArea_mm2: 0.18; SizeAreaWB_mm2: 2.08; SizeX_mm: 0.6; SizeY_mm: 0.3; SizeZ_mm: 0.26; AEC Category: Q200; Green_Lifecycle: Active; Green_REACh: Passed
signal-integrity model Cap
simulation model Cap
footprint 0201
footprint 0201M
footprint 0201L
footprint 0201_Silk
pins: 1, 2

## CL03A105MP3NSNC
designator C?  ValueDisplayed: 1µF  (hidden comment: CL03A105MP3NSNC)
CAP, CERM, 1 µF, 10 V,+/- 20%, X5R, 0201; Manufacturer: Samsung Electro-Mechanics; Polarized: N; CompType: Capacitor; Value: 1uF; U/M: EA; Cap_F: 0.000001; Tolerance_%: 20; VDC_V: 10; Value2: 10V; TaMin_C: -55; TaMax_C: 85; Cap_Case: 0201; SizeArea_mm2: 0.18; SizeAreaWB_mm2: 2.08; SizeX_mm: 0.6; SizeY_mm: 0.3; SizeZ_mm: 0.26; AEC Category: Q200; Green_Lifecycle: Active; Green_REACh: Passed
signal-integrity model Cap
simulation model Cap
footprint 0201
footprint 0201M
footprint 0201L
footprint 0201_Silk
pins: 1, 2

## CL03A225MQ3CRNC
designator C?  ValueDisplayed: 2.2µF  (hidden comment: CL03A225MQ3CRNC)
CAP, CERM, 2.2 µF, 6.3 V,+/- 20%, X5R, 0201; Manufacturer: Samsung Electro-Mechanics; Polarized: N; CompType: Capacitor; Value: 2.2uF; U/M: EA; Cap_F: 0.0000022; Tolerance_%: 20; VDC_V: 6.3; Value2: 6.3V; TaMin_C: -55; TaMax_C: 85; Cap_Case: 0201; SizeArea_mm2: 0.18; SizeAreaWB_mm2: 2.08; SizeX_mm: 0.6; SizeY_mm: 0.3; SizeZ_mm: 0.26; AEC Category: Q200; Green_Lifecycle: Active; Green_REACh: Passed
signal-integrity model Cap
simulation model Cap
footprint 0201
footprint 0201M
footprint 0201L
footprint 0201_Silk
pins: 1, 2

## CL03A474KQ3NNNC
designator C?  ValueDisplayed: 0.47µF  (hidden comment: CL03A474KQ3NNNC)
CAP, CERM, 0.47 µF, 6.3 V,+/- 10%, X5R, 0201; Manufacturer: Samsung Electro-Mechanics; Polarized: N; CompType: Capacitor; Value: 0.47uF; U/M: EA; Cap_F: 0.00000047; Tolerance_%: 10; VDC_V: 6.3; Value2: 6.3V; TaMin_C: -55; TaMax_C: 85; Cap_Case: 0201; SizeArea_mm2: 0.18; SizeAreaWB_mm2: 2.08; SizeX_mm: 0.6; SizeY_mm: 0.3; SizeZ_mm: 0.33; AEC Category: Q200
signal-integrity model Cap
simulation model Cap
footprint 0201_033
footprint 0201_033M
footprint 0201_033L
pins: 1, 2

## CL05A106MP5NUNC
designator C?  ValueDisplayed: 10µF  (hidden comment: CL05A106MP5NUNC)
CAP, CERM, 10 µF, 10 V,+/- 20%, X5R, 0402; Manufacturer: Samsung Electro-Mechanics; Polarized: N; CompType: Capacitor; Value: 10uF; U/M: EA; Cap_F: 0.00001; Tolerance_%: 20; VDC_V: 10; Value2: 10V; TaMin_C: -55; TaMax_C: 85; Cap_Case: 0402; SizeArea_mm2: 0.5; SizeAreaWB_mm2: 3; SizeX_mm: 1; SizeZ_mm: 0.6; AEC Category: Q200; Green_Lifecycle: Active; Green_REACh: Passed
signal-integrity model Cap
simulation model Cap
footprint 0402
footprint 0402M
footprint 0402L
footprint 0402S
pins: 1, 2

## CL05A106MQ5NUNC
designator C?  ValueDisplayed: 10µF  (hidden comment: CL05A106MQ5NUNC)
CAP, CERM, 10 µF, 6.3 V,+/- 20%, X5R, 0402; Manufacturer: Samsung Electro-Mechanics; Polarized: N; CompType: Capacitor; Value: 10uF; U/M: EA; Cap_F: 0.00001; Tolerance_%: 20; VDC_V: 6.3; Value2: 6.3V; TaMin_C: -55; TaMax_C: 85; Cap_Case: 0402; SizeArea_mm2: 0.5; SizeAreaWB_mm2: 3; SizeX_mm: 1; SizeZ_mm: 0.6; AEC Category: Q200; Green_Lifecycle: Active; Green_REACh: Passed
signal-integrity model Cap
simulation model Cap
footprint 0402
footprint 0402M
footprint 0402L
footprint 0402S
pins: 1, 2

## CL05A225KQ5NNNC
designator C?  ValueDisplayed: 2.2µF  (hidden comment: CL05A225KQ5NNNC)
CAP, CERM, 2.2 µF, 6.3 V,+/- 10%, X5R, 0402; Manufacturer: Samsung Electro-Mechanics; Polarized: N; CompType: Capacitor; Value: 2.2uF; U/M: EA; Cap_F: 0.0000022; Tolerance_%: 10; VDC_V: 6.3; Value2: 6.3V; TaMin_C: -55; TaMax_C: 85; Cap_Case: 0402; SizeArea_mm2: 0.5; SizeAreaWB_mm2: 3; SizeX_mm: 1; SizeZ_mm: 0.6; AEC Category: Q200; Green_Lifecycle: Active; Green_REACh: Passed
signal-integrity model Cap
simulation model Cap
footprint 0402
footprint 0402M
footprint 0402L
footprint 0402S
pins: 1, 2

## CL05A475MP5NRNC
designator C?  ValueDisplayed: 4.7µF  (hidden comment: CL05A475MP5NRNC)
CAP, CERM, 4.7 µF, 10 V,+/- 20%, X5R, 0402; Manufacturer: Samsung Electro-Mechanics; Polarized: N; CompType: Capacitor; Value: 4.7uF; U/M: EA; Cap_F: 0.0000047; Tolerance_%: 20; VDC_V: 10; Value2: 10V; TaMin_C: -55; TaMax_C: 85; Cap_Case: 0402; SizeArea_mm2: 0.5; SizeAreaWB_mm2: 3; SizeX_mm: 1; SizeZ_mm: 0.6; AEC Category: Q200; Green_Lifecycle: Active; Green_REACh: Passed
signal-integrity model Cap
simulation model Cap
footprint 0402
footprint 0402M
footprint 0402L
footprint 0402S
pins: 1, 2

## CL05A475MQ5NRNC
designator C?  ValueDisplayed: 4.7µF  (hidden comment: CL05A475MQ5NRNC)
CAP, CERM, 4.7 µF, 6.3 V,+/- 20%, X5R, 0402; Manufacturer: Samsung Electro-Mechanics; Polarized: N; CompType: Capacitor; Value: 4.7uF; U/M: EA; Cap_F: 0.0000047; Tolerance_%: 20; VDC_V: 6.3; Value2: 6.3V; TaMin_C: -55; TaMax_C: 85; Cap_Case: 0402; SizeArea_mm2: 0.5; SizeAreaWB_mm2: 3; SizeX_mm: 1; SizeZ_mm: 0.6; AEC Category: Q200; Green_Lifecycle: Active; Green_REACh: Passed
signal-integrity model Cap
simulation model Cap
footprint 0402
footprint 0402M
footprint 0402L
footprint 0402S
pins: 1, 2

## CL05B104KP5NNNC
designator C?  ValueDisplayed: 0.1µF  (hidden comment: CL05B104KP5NNNC)
CAP, CERM, 0.1 µF, 10 V,+/- 10%, X7R, 0402; Manufacturer: Samsung Electro-Mechanics; Polarized: N; CompType: Capacitor; Value: 0.1uF; U/M: EA; Cap_F: 0.0000001; Tolerance_%: 10; Value2: 10V; TaMin_C: -55; TaMax_C: 125; Cap_Case: 0402; SizeArea_mm2: 0.5; SizeAreaWB_mm2: 3; SizeX_mm: 1; SizeZ_mm: 0.6; AEC Category: Q200; Green_Lifecycle: Active; Green_REACh: Passed
signal-integrity model Cap
simulation model Cap
footprint 0402
footprint 0402M
footprint 0402L
footprint 0402S
pins: 1, 2

## CL05B222JB5NNNC
designator C?  ValueDisplayed: 2200pF  (hidden comment: CL05B222JB5NNNC)
CAP, CERM, 2200 pF, 50 V,+/- 5%, X7R, 0402; Manufacturer: Samsung Electro-Mechanics; Polarized: N; CompType: Capacitor; Value: 2200pF; U/M: EA; Cap_F: 0.0000000022; Tolerance_%: 5; VDC_V: 50; Value2: 50V; TaMin_C: -55; TaMax_C: 125; Cap_Case: 0402; SizeArea_mm2: 0.5; SizeAreaWB_mm2: 3; SizeX_mm: 1; SizeZ_mm: 0.6; AEC Category: Q200
signal-integrity model Cap
simulation model Cap
footprint 0402
footprint 0402M
footprint 0402L
footprint 0402S
pins: 1, 2

## CL05B333KO5NFNC
designator C?  ValueDisplayed: 0.033µF  (hidden comment: CL05B333KO5NFNC)
CAP, CERM, 0.033 µF, 16 V,+/- 10%, X7R, 0402; Manufacturer: Samsung Electro-Mechanics; Polarized: N; CompType: Capacitor; Value: 0.033uF; U/M: EA; Cap_F: 0.000000033; Tolerance_%: 10; VDC_V: 16; Value2: 16V; TaMin_C: -55; TaMax_C: 125; Cap_Case: 0402; SizeArea_mm2: 0.5; SizeAreaWB_mm2: 3; SizeX_mm: 1; SizeZ_mm: 0.6; AEC Category: Q200
signal-integrity model Cap
simulation model Cap
footprint 0402
footprint 0402M
footprint 0402L
footprint 0402S
pins: 1, 2

## CL05C120JB5NNNC
designator C?  ValueDisplayed: 12pF  (hidden comment: CL05C120JB5NNNC)
CAP, CERM, 12 pF, 50 V,+/- 5%, C0G/NP0, 0402; Manufacturer: Samsung Electro-Mechanics; Polarized: N; CompType: Capacitor; Value: 12pF; U/M: EA; Cap_F: 0.000000000012; Tolerance_%: 5; VDC_V: 50; Value2: 50V; TaMin_C: -55; TaMax_C: 125; Cap_Case: 0402; SizeArea_mm2: 0.5; SizeAreaWB_mm2: 3; SizeX_mm: 1; SizeZ_mm: 0.6; AEC Category: Q200
signal-integrity model Cap
simulation model Cap
footprint 0402
footprint 0402M
footprint 0402L
footprint 0402S
pins: 1, 2

## CL05C561JB5NNNC
designator C?  ValueDisplayed: 560pF  (hidden comment: CL05C561JB5NNNC)
CAP, CERM, 560 pF, 50 V,+/- 5%, C0G/NP0, 0402; Manufacturer: Samsung Electro-Mechanics; Polarized: N; CompType: Capacitor; Value: 560pF; U/M: EA; Cap_F: 0.00000000056; Tolerance_%: 5; VDC_V: 50; Value2: 50V; TaMin_C: -55; TaMax_C: 125; Cap_Case: 0402; SizeArea_mm2: 0.5; SizeAreaWB_mm2: 3; SizeX_mm: 1; SizeZ_mm: 0.6; AEC Category: Q200
signal-integrity model Cap
simulation model Cap
footprint 0402
footprint 0402M
footprint 0402L
footprint 0402S
pins: 1, 2

## CL10A106MQ8NNNC
designator C?  ValueDisplayed: 10µF  (hidden comment: CL10A106MQ8NNNC)
CAP, CERM, 10 µF, 6.3 V,+/- 20%, X5R, 0603; Manufacturer: Samsung Electro-Mechanics; Polarized: N; CompType: Capacitor; Value: 10uF; U/M: EA; Cap_F: 0.00001; Tolerance_%: 20; VDC_V: 6.3; Value2: 6.3V; TaMin_C: -55; TaMax_C: 85; Cap_Case: 0603; SizeArea_mm2: 1.28; SizeAreaWB_mm2: 4.68; SizeX_mm: 1.6; SizeY_mm: 0.8; SizeZ_mm: 1; AEC Category: Q200; Green_Lifecycle: Active; Green_REACh: Passed
signal-integrity model Cap
simulation model Cap
footprint 0603
footprint 0603M
footprint 0603L
footprint 0603_HV
footprint 0603S
pins: 1, 2

## CL10A226MP8NUNE
designator C?  ValueDisplayed: 22µF  (hidden comment: CL10A226MP8NUNE)
CAP, CERM, 22 µF, 10 V,+/- 20%, X5R, 0603; Manufacturer: Samsung Electro-Mechanics; Polarized: N; CompType: Capacitor; Value: 22uF; U/M: EA; Cap_F: 0.000022; Tolerance_%: 20; VDC_V: 10; Value2: 10V; TaMin_C: -55; TaMax_C: 85; Cap_Case: 0603; SizeArea_mm2: 1.28; SizeAreaWB_mm2: 4.68; SizeX_mm: 1.6; SizeY_mm: 0.8; SizeZ_mm: 1; AEC Category: Q200; Green_Lifecycle: Active; Green_REACh: Passed
signal-integrity model Cap
simulation model Cap
footprint 0603
footprint 0603M
footprint 0603L
footprint 0603_HV
footprint 0603S
pins: 1, 2

## CL10B103KB8NCNC
designator C?  ValueDisplayed: 0.01µF  (hidden comment: CL10B103KB8NCNC)
CAP, CERM, 0.01 µF, 50 V,+/- 10%, X7R, 0603; Manufacturer: Samsung Electro-Mechanics; Polarized: N; CompType: Capacitor; Value: 0.01uF; U/M: EA; Cap_F: 0.00000001; Tolerance_%: 10; VDC_V: 50; Value2: 50V; TaMin_C: -55; TaMax_C: 125; Cap_Case: 0603; SizeArea_mm2: 1.28; SizeAreaWB_mm2: 4.68; SizeX_mm: 1.6; SizeY_mm: 0.8; SizeZ_mm: 1; AEC Category: Q200; Green_Lifecycle: Active; Green_REACh: Passed
signal-integrity model Cap
simulation model Cap
footprint 0603
footprint 0603M
footprint 0603L
footprint 0603_HV
footprint 0603S
pins: 1, 2

## CL10B104KO8NNNC
designator C?  ValueDisplayed: 0.1µF  (hidden comment: CL10B104KO8NNNC)
CAP, CERM, 0.1 µF, 16 V,+/- 10%, X7R, 0603; Manufacturer: Samsung Electro-Mechanics; Polarized: N; CompType: Capacitor; Value: 0.1uF; U/M: EA; Cap_F: 0.0000001; Tolerance_%: 10; VDC_V: 16; Value2: 16V; TaMin_C: -55; TaMax_C: 125; Cap_Case: 0603; SizeArea_mm2: 1.28; SizeAreaWB_mm2: 4.68; SizeX_mm: 1.6; SizeY_mm: 0.8; SizeZ_mm: 1; AEC Category: Q200; Green_Lifecycle: Active; Green_REACh: Passed
signal-integrity model Cap
simulation model Cap
footprint 0603
footprint 0603M
footprint 0603L
footprint 0603_HV
footprint 0603S
pins: 1, 2

## CL10B105KQ8NNNC
designator C?  ValueDisplayed: 1µF  (hidden comment: CL10B105KQ8NNNC)
CAP, CERM, 1 µF, 6.3 V,+/- 10%, X7R, 0603; Manufacturer: Samsung Electro-Mechanics; Polarized: N; CompType: Capacitor; Value: 1uF; U/M: EA; Cap_F: 0.000001; Tolerance_%: 10; VDC_V: 6.3; Value2: 6.3V; TaMin_C: -55; TaMax_C: 125; Cap_Case: 0603; SizeArea_mm2: 1.28; SizeAreaWB_mm2: 4.68; SizeX_mm: 1.6; SizeY_mm: 0.8; SizeZ_mm: 1; AEC Category: Q200; Green_Lifecycle: Active; Green_REACh: Passed
signal-integrity model Cap
simulation model Cap
footprint 0603
footprint 0603M
footprint 0603L
footprint 0603_HV
footprint 0603S
pins: 1, 2

## CL10B475KQ8NQND
designator C?  ValueDisplayed: 4.7µF  (hidden comment: CL10B475KQ8NQND)
CAP, CERM, 4.7 µF, 6.3 V,+/- 10%, X7R, 0603; Manufacturer: Samsung Electro-Mechanics; Polarized: N; CompType: Capacitor; Value: 4.7uF; U/M: EA; Cap_F: 0.0000047; Tolerance_%: 10; VDC_V: 6.3; Value2: 6.3V; TaMin_C: -55; TaMax_C: 125; Cap_Case: 0603; SizeArea_mm2: 1.28; SizeAreaWB_mm2: 4.68; SizeX_mm: 1.6; SizeY_mm: 0.8; SizeZ_mm: 1; AEC Category: Q200
signal-integrity model Cap
simulation model Cap
footprint 0603
footprint 0603M
footprint 0603L
footprint 0603_HV
footprint 0603S
pins: 1, 2

## CL10C1R2BB8NNNC
designator C?  ValueDisplayed: 1.2pF  (hidden comment: CL10C1R2BB8NNNC)
CAP, CERM, 1.2 pF, 50 V,+/- 10%, C0G/NP0, 0603; Manufacturer: Samsung Electro-Mechanics; Polarized: N; CompType: Capacitor; Value: 1.2pF; U/M: EA; Cap_F: 0.0000000000012; Tolerance_%: 10; VDC_V: 50; Value2: 50V; TaMin_C: -55; TaMax_C: 125; Cap_Case: 0603; SizeArea_mm2: 1.28; SizeAreaWB_mm2: 4.68; SizeX_mm: 1.6; SizeY_mm: 0.8; SizeZ_mm: 1; AEC Category: Q200
signal-integrity model Cap
simulation model Cap
footprint 0603
footprint 0603M
footprint 0603L
footprint 0603_HV
footprint 0603S
pins: 1, 2

## CL10C030BB8NNNC
designator C?  ValueDisplayed: 3pF  (hidden comment: CL10C030BB8NNNC)
CAP, CERM, 3 pF, 50 V,+/- 3%, C0G/NP0, 0603; Manufacturer: Samsung Electro-Mechanics; Polarized: N; CompType: Capacitor; Value: 3pF; U/M: EA; Cap_F: 0.000000000003; Tolerance_%: 3; VDC_V: 50; Value2: 50V; TaMin_C: -55; TaMax_C: 125; Cap_Case: 0603; SizeArea_mm2: 1.28; SizeAreaWB_mm2: 4.68; SizeX_mm: 1.6; SizeY_mm: 0.8; SizeZ_mm: 1; AEC Category: Q200
signal-integrity model Cap
simulation model Cap
footprint 0603
footprint 0603M
footprint 0603L
footprint 0603_HV
footprint 0603S
pins: 1, 2

## CL10C102JB8NNNC
designator C?  ValueDisplayed: 1000pF  (hidden comment: CL10C102JB8NNNC)
CAP, CERM, 1000 pF, 50 V,+/- 5%, X7R, 0603; Manufacturer: Samsung Electro-Mechanics; Polarized: N; CompType: Capacitor; Value: 1000pF; U/M: EA; Cap_F: 0.000000001; Tolerance_%: 5; VDC_V: 50; Value2: 50V; TaMin_C: -55; TaMax_C: 125; Cap_Case: 0603; SizeArea_mm2: 1.28; SizeAreaWB_mm2: 4.68; SizeX_mm: 1.6; SizeY_mm: 0.8; SizeZ_mm: 1; AEC Category: Q200; Green_Lifecycle: Active; Green_REACh: Passed
signal-integrity model Cap
simulation model Cap
footprint 0603
footprint 0603M
footprint 0603L
footprint 0603_HV
footprint 0603S
pins: 1, 2

## CL10C270FB8NNNC
designator C?  ValueDisplayed: 27pF  (hidden comment: CL10C270FB8NNNC)
CAP, CERM, 27 pF, 50 V,+/- 1%, C0G/NP0, 0603; Manufacturer: Samsung Electro-Mechanics; Polarized: N; CompType: Capacitor; Value: 27pF; U/M: EA; Cap_F: 0.000000000027; Tolerance_%: 1; VDC_V: 50; Value2: 50V; TaMin_C: -55; TaMax_C: 125; Cap_Case: 0603; SizeArea_mm2: 1.28; SizeAreaWB_mm2: 4.68; SizeX_mm: 1.6; SizeY_mm: 0.8; AEC Category: Q200; Green_Lifecycle: Active; Green_REACh: Passed
signal-integrity model Cap
simulation model Cap
footprint 0603
footprint 0603M
footprint 0603L
footprint 0603_HV
footprint 0603S
pins: 1, 2

## CL10C330FB8NNNC
designator C?  ValueDisplayed: 33pF  (hidden comment: CL10C330FB8NNNC)
CAP, CERM, 33 pF, 50 V,+/- 5%, C0G/NP0, 0603; Manufacturer: Samsung Electro-Mechanics; Polarized: N; CompType: Capacitor; Value: 33pF; U/M: EA; Cap_F: 0.000000000033; Tolerance_%: 5; VDC_V: 50; Value2: 50V; TaMin_C: -55; TaMax_C: 125; Cap_Case: 0603; SizeArea_mm2: 1.28; SizeAreaWB_mm2: 4.68; SizeX_mm: 1.6; SizeY_mm: 0.8; SizeZ_mm: 1; AEC Category: Q200; Green_Lifecycle: Active; Green_REACh: Passed
signal-integrity model Cap
simulation model Cap
footprint 0603
footprint 0603M
footprint 0603L
footprint 0603_HV
footprint 0603S
pins: 1, 2

## CL21A106KAFN3NE
designator C?  ValueDisplayed: 10µF  (hidden comment: CL21A106KAFN3NE)
CAP, CERM, 10 µF, 25 V,+/- 10%, X5R, 0805; Manufacturer: Samsung Electro-Mechanics; Polarized: N; CompType: Capacitor; Value: 10uF; U/M: EA; Cap_F: 0.00001; Tolerance_%: 10; VDC_V: 25; Value2: 25V; TaMin_C: -55; TaMax_C: 85; Cap_Case: 0805; SizeArea_mm2: 2.5; SizeAreaWB_mm2: 6.75; SizeX_mm: 2; SizeY_mm: 1.25; SizeZ_mm: 1.45; AEC Category: Q200; Green_Lifecycle: Active; Green_REACh: Passed
signal-integrity model Cap
simulation model Cap
footprint 0805_HV
footprint 0805_HV1
footprint 0805
footprint 0805M
footprint 0805L
pins: 1, 2

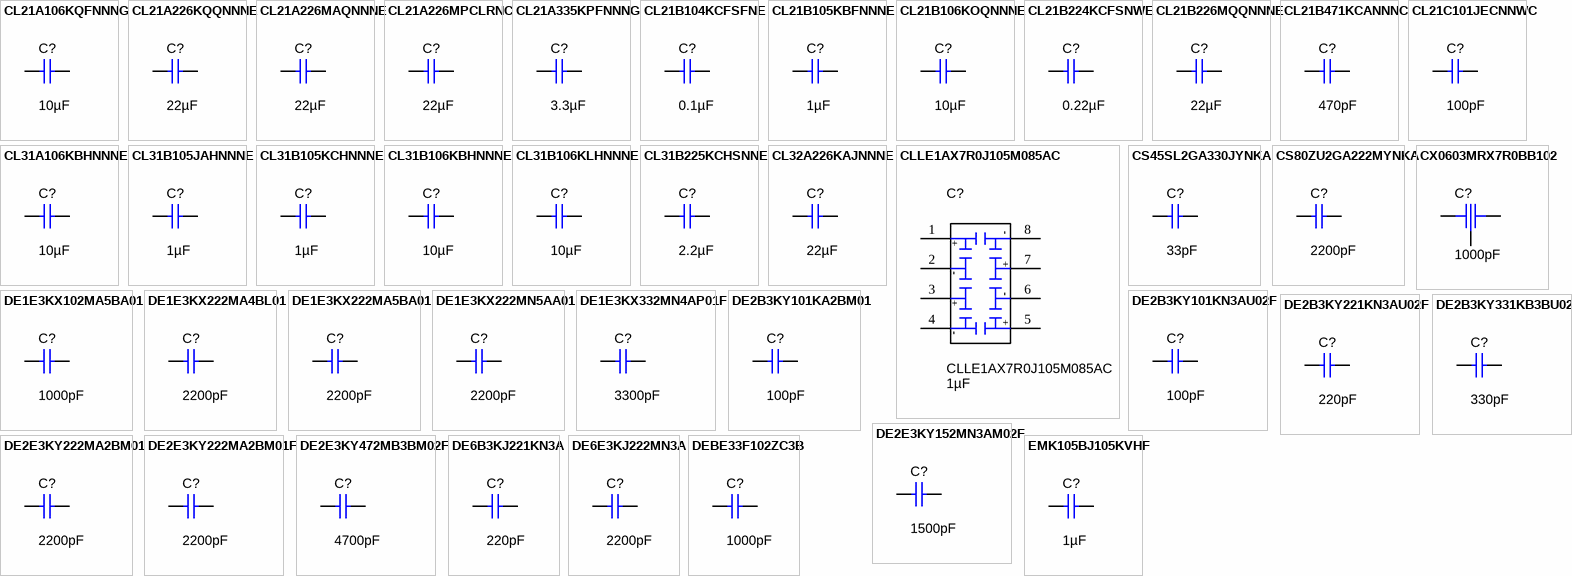
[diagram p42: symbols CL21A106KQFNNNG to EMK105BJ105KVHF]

## CL21A106KQFNNNG
designator C?  ValueDisplayed: 10µF  (hidden comment: CL21A106KQFNNNG)
CAP, CERM, 10 µF, 6.3 V,+/- 10%, X5R, 0805; Manufacturer: Samsung Electro-Mechanics; Polarized: N; CompType: Capacitor; Value: 10uF; U/M: EA; Cap_F: 0.00001; Tolerance_%: 10; VDC_V: 6.3; Value2: 6.3V; TaMin_C: -55; TaMax_C: 85; Cap_Case: 0805; SizeArea_mm2: 2.5; SizeAreaWB_mm2: 6.75; SizeX_mm: 2; SizeY_mm: 1.25; SizeZ_mm: 1.45; AEC Category: Q200
signal-integrity model Cap
simulation model Cap
footprint 0805_HV
footprint 0805_HV1
footprint 0805
footprint 0805M
footprint 0805L
pins: 1, 2

## CL21A226KQQNNNE
designator C?  ValueDisplayed: 22µF  (hidden comment: CL21A226KQQNNNE)
CAP, CERM, 22 µF, 6.3 V,+/- 10%, X5R, 0805; Manufacturer: Samsung Electro-Mechanics; Polarized: N; CompType: Capacitor; Value: 22uF; U/M: EA; Cap_F: 0.000022; Tolerance_%: 10; VDC_V: 6.3; Value2: 6.3V; TaMin_C: -55; TaMax_C: 85; Cap_Case: 0805; SizeArea_mm2: 2.5; SizeAreaWB_mm2: 6.75; SizeX_mm: 2; SizeY_mm: 1.25; SizeZ_mm: 1.45; AEC Category: Q200; Green_Lifecycle: Active; Green_REACh: Passed
signal-integrity model Cap
simulation model Cap
footprint 0805_HV
footprint 0805_HV1
footprint 0805
footprint 0805M
footprint 0805L
pins: 1, 2

## CL21A226MAQNNNE
designator C?  ValueDisplayed: 22µF  (hidden comment: CL21A226MAQNNNE)
CAP, CERM, 22 µF, 25 V,+/- 20%, X5R, 0805; Manufacturer: Samsung Electro-Mechanics; Polarized: N; CompType: Capacitor; Value: 22uF; U/M: EA; Cap_F: 0.000022; Tolerance_%: 20; VDC_V: 25; Value2: 25V; TaMin_C: -55; TaMax_C: 85; Cap_Case: 0805; SizeArea_mm2: 2.5; SizeAreaWB_mm2: 6.75; SizeX_mm: 2; SizeY_mm: 1.25; SizeZ_mm: 1.45; AEC Category: Q200
signal-integrity model Cap
simulation model Cap
footprint 0805_HV
footprint 0805_HV1
footprint 0805
footprint 0805M
footprint 0805L
pins: 1, 2

## CL21A226MPCLRNC
designator C?  ValueDisplayed: 22µF  (hidden comment: CL21A226MPCLRNC)
CAP, CERM, 22 µF, 10 V,+/- 20%, X5R, 0805; Manufacturer: Samsung Electro-Mechanics; Polarized: N; CompType: Capacitor; Value: 22uF; U/M: EA; Cap_F: 0.000022; Tolerance_%: 20; VDC_V: 10; Value2: 10V; TaMin_C: -55; TaMax_C: 85; Cap_Case: 0805; SizeArea_mm2: 2.5; SizeAreaWB_mm2: 6.75; SizeX_mm: 2; SizeY_mm: 1.25; SizeZ_mm: 1.45; AEC Category: Q200; Green_Lifecycle: Active; Green_REACh: Passed
signal-integrity model Cap
simulation model Cap
footprint 0805_HV
footprint 0805_HV1
footprint 0805
footprint 0805M
footprint 0805L
pins: 1, 2

## CL21A335KPFNNNG
designator C?  ValueDisplayed: 3.3µF  (hidden comment: CL21A335KPFNNNG)
CAP, CERM, 3.3 µF, 10 V,+/- 10%, X5R, 0805; Manufacturer: Samsung Electro-Mechanics; Polarized: N; CompType: Capacitor; Value: 3.3uF; U/M: EA; Cap_F: 0.0000033; Tolerance_%: 10; Value2: 10V; TaMin_C: -55; TaMax_C: 85; Cap_Case: 0805; SizeArea_mm2: 2.5; SizeAreaWB_mm2: 6.75; SizeX_mm: 2; SizeY_mm: 1.25; SizeZ_mm: 1.45; AEC Category: Q200
signal-integrity model Cap
simulation model Cap
footprint 0805_HV
footprint 0805_HV1
footprint 0805
footprint 0805M
footprint 0805L
pins: 1, 2

## CL21B104KCFSFNE
designator C?  ValueDisplayed: 0.1µF  (hidden comment: CL21B104KCFSFNE)
CAP, CERM, 0.1 µF, 100 V,+/- 10%, X7R, 0805; Manufacturer: Samsung Electro-Mechanics; Polarized: N; CompType: Capacitor; Value: 0.1uF; U/M: EA; Cap_F: 0.0000001; Tolerance_%: 10; VDC_V: 100; Value2: 100V; TaMin_C: -55; TaMax_C: 125; Cap_Case: 0805; SizeArea_mm2: 2.5; SizeAreaWB_mm2: 6.75; SizeX_mm: 2; SizeY_mm: 1.25; SizeZ_mm: 1.45; AEC Category: Q200; Green_Lifecycle: Active; Green_REACh: Passed
signal-integrity model Cap
simulation model Cap
footprint 0805_HV
footprint 0805_HV1
footprint 0805
footprint 0805M
footprint 0805L
pins: 1, 2

## CL21B105KBFNNNE
designator C?  ValueDisplayed: 1µF  (hidden comment: CL21B105KBFNNNE)
CAP, CERM, 1 µF, 50 V,+/- 10%, X7R, 0805; Manufacturer: Samsung Electro-Mechanics; Polarized: N; CompType: Capacitor; Value: 1uF; U/M: EA; Cap_F: 0.000001; Tolerance_%: 10; VDC_V: 50; Value2: 50V; TaMin_C: -55; TaMax_C: 125; Cap_Case: 0805; SizeArea_mm2: 2.5; SizeAreaWB_mm2: 6.75; SizeX_mm: 2; SizeY_mm: 1.25; SizeZ_mm: 1.45; AEC Category: Q200; Green_Lifecycle: Active; Green_REACh: Passed
signal-integrity model Cap
simulation model Cap
footprint 0805_HV
footprint 0805_HV1
footprint 0805
footprint 0805M
footprint 0805L
pins: 1, 2

## CL21B106KOQNNNE
designator C?  ValueDisplayed: 10µF  (hidden comment: CL21B106KOQNNNE)
CAP, CERM, 10 µF, 16 V,+/- 10%, X7R, 0805; Manufacturer: Samsung Electro-Mechanics; Polarized: N; CompType: Capacitor; Value: 10uF; U/M: EA; Cap_F: 0.00001; Tolerance_%: 10; VDC_V: 16; Value2: 16V; TaMin_C: -55; TaMax_C: 125; Cap_Case: 0805; SizeArea_mm2: 2.5; SizeAreaWB_mm2: 6.75; SizeX_mm: 2; SizeY_mm: 1.25; SizeZ_mm: 1.45; AEC Category: Q200; Green_Lifecycle: Active; Green_REACh: Passed
signal-integrity model Cap
simulation model Cap
footprint 0805_HV
footprint 0805_HV1
footprint 0805
footprint 0805M
footprint 0805L
pins: 1, 2

## CL21B224KCFSNWE
designator C?  ValueDisplayed: 0.22µF  (hidden comment: CL21B224KCFSNWE)
CAP, CERM, 0.22 µF, 100 V,+/- 10%, X7R, 0805; Manufacturer: Samsung Electro-Mechanics; Polarized: N; CompType: Capacitor; Value: 0.22uF; U/M: EA; Cap_F: 0.00000022; Tolerance_%: 10; VDC_V: 100; Value2: 100V; TaMin_C: -55; TaMax_C: 125; Cap_Case: 0805; SizeArea_mm2: 2.5; SizeAreaWB_mm2: 6.75; SizeX_mm: 2; SizeY_mm: 1.25; SizeZ_mm: 1.45; AEC Category: Q200; Green_Lifecycle: Active; Green_REACh: Passed
signal-integrity model Cap
simulation model Cap
footprint 0805_HV
footprint 0805_HV1
footprint 0805
footprint 0805M
footprint 0805L
pins: 1, 2

## CL21B226MQQNNNE
designator C?  ValueDisplayed: 22µF  (hidden comment: CL21B226MQQNNNE)
CAP, CERM, 22 µF, 6.3 V,+/- 20%, X7R, 0805; Manufacturer: Samsung Electro-Mechanics; Polarized: N; CompType: Capacitor; Value: 22uF; U/M: EA; Cap_F: 0.000022; Tolerance_%: 20; VDC_V: 6.3; Value2: 6.3V; TaMin_C: -55; TaMax_C: 125; Cap_Case: 0805; SizeArea_mm2: 2.5; SizeAreaWB_mm2: 6.75; SizeX_mm: 2; SizeY_mm: 1.25; SizeZ_mm: 1.45; AEC Category: Q200
signal-integrity model Cap
simulation model Cap
footprint 0805_HV
footprint 0805_HV1
footprint 0805
footprint 0805M
footprint 0805L
pins: 1, 2

## CL21B471KCANNNC
designator C?  ValueDisplayed: 470pF  (hidden comment: CL21B471KCANNNC)
CAP, CERM, 470 pF, 100 V,+/- 10%, X7R, 0805; Manufacturer: Samsung Electro-Mechanics; Polarized: N; CompType: Capacitor; Value: 470pF; U/M: EA; Cap_F: 0.00000000047; Tolerance_%: 10; VDC_V: 100; Value2: 100V; TaMin_C: -55; TaMax_C: 125; Cap_Case: 0805; SizeArea_mm2: 2.5; SizeAreaWB_mm2: 6.75; SizeX_mm: 2; SizeY_mm: 1.25; SizeZ_mm: 1.45; AEC Category: Q200
signal-integrity model Cap
simulation model Cap
footprint 0805_HV
footprint 0805_HV1
footprint 0805
footprint 0805M
footprint 0805L
pins: 1, 2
